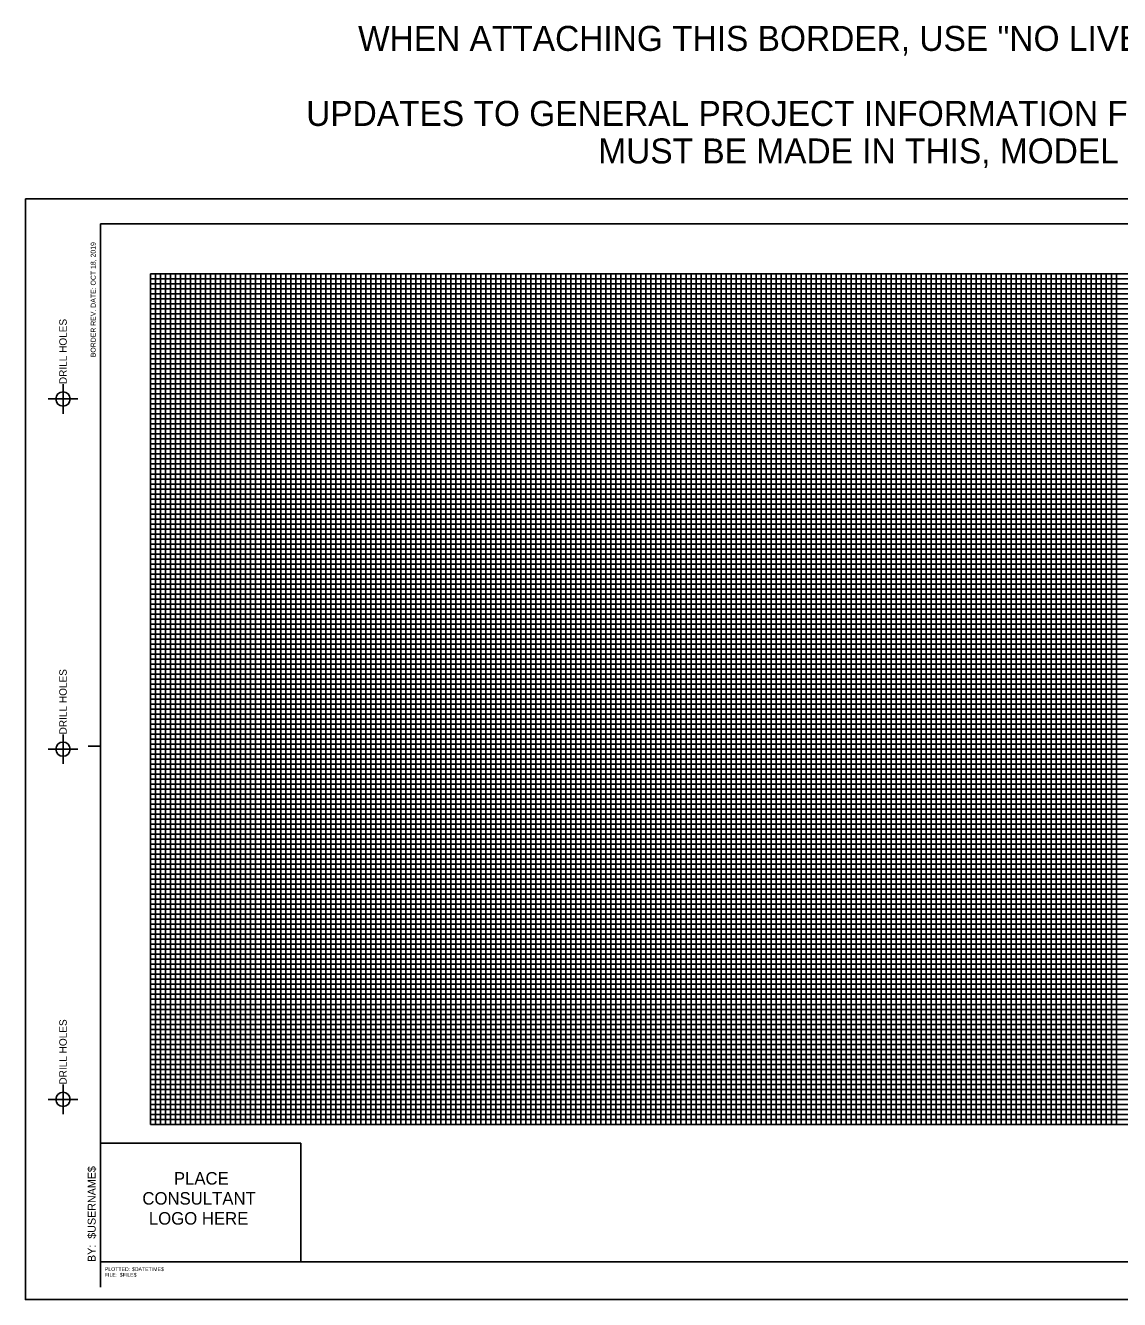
# Model space of a CAD drawing. Extents: x 0 to 34, y 0 to 25.5.
# Drawn here: x 0 to 21.86, y 0 to 25.46 of the extents above; entities that cross this region are included whole.
import ezdxf

# ---------------------------------------------------------------- set-up
doc = ezdxf.new("R2010")
doc.units = 0
for name, color, linetype in [('BORD-LINE', 7, 'Continuous'), ('CONS-LINE', 7, 'Continuous'), ('CONS-LOGO', 7, 'Continuous'), ('TTLB-TEXT', 7, 'Continuous'), ('USER-PAGE', 7, 'Continuous'), ('USER-TEXT', 7, 'Continuous'), ('XSEC-MAJR', 7, 'Continuous'), ('XSEC-MINR', 7, 'Continuous')]:
    doc.layers.add(name, color=color, linetype=linetype)

msp = doc.modelspace()

# ---------------------------------------------------------------- linework, layer by layer
at = {"layer": 'BORD-LINE'}
for p, q in [((33.5, 21.5), (1.5, 21.5)), ((1.5, 21.5), (1.5, 0.75)), ((1.5, 11.062), (1.25, 11.062)), ((1.5, 0.75), (33.5, 0.75)), ((1.5, 0.75), (1.5, 0.25))]:
    msp.add_line(p, q, dxfattribs=at)
at = {"layer": 'CONS-LINE'}
for p, q in [((1.5, 3.125), (5.5, 3.125)), ((5.5, 3.125), (5.5, 0.75))]:
    msp.add_line(p, q, dxfattribs=at)
at = {"layer": 'TTLB-TEXT'}
for p, q in [((0.75, 18.296), (0.75, 18)), ((0.454, 18), (1.046, 18)), ((0.75, 18), (0.75, 17.704)), ((0.75, 11.296), (0.75, 11)), ((1.046, 11), (0.454, 11)), ((0.75, 11), (0.75, 10.704)), ((0.75, 4.296), (0.75, 3.704)), ((0.454, 4), (1.046, 4))]:
    msp.add_line(p, q, dxfattribs=at)
for centre in [(0.75, 18), (0.75, 11), (0.75, 4)]:
    msp.add_circle(centre, 0.143, dxfattribs=at)
at = {"layer": 'USER-PAGE'}
msp.add_lwpolyline([(0, 22), (34, 22), (34, 0), (0, 0)], close=True, dxfattribs=at)
at = {"layer": 'XSEC-MAJR'}
for p, q in [((2.5, 20.5), (2.5, 3.5)), ((32.5, 20.5), (2.5, 20.5)), ((3.5, 20.5), (3.5, 3.5)), ((4.5, 20.5), (4.5, 3.5)), ((5.5, 20.5), (5.5, 3.5)), ((6.5, 20.5), (6.5, 3.5)), ((7.5, 20.5), (7.5, 3.5)), ((8.5, 20.5), (8.5, 3.5)), ((9.5, 20.5), (9.5, 3.5)), ((10.5, 20.5), (10.5, 3.5)), ((11.5, 20.5), (11.5, 3.5)), ((12.5, 20.5), (12.5, 3.5)), ((13.5, 20.5), (13.5, 3.5)), ((14.5, 20.5), (14.5, 3.5)), ((15.5, 20.5), (15.5, 3.5)), ((16.5, 20.5), (16.5, 3.5)), ((17.5, 20.5), (17.5, 3.5)), ((18.5, 20.5), (18.5, 3.5)), ((19.5, 20.5), (19.5, 3.5)), ((20.5, 20.5), (20.5, 3.5)), ((21.5, 20.5), (21.5, 3.5)), ((32.5, 19.5), (2.5, 19.5)), ((32.5, 18.5), (2.5, 18.5)), ((32.5, 17.5), (2.5, 17.5)), ((32.5, 16.5), (2.5, 16.5)), ((32.5, 15.5), (2.5, 15.5)), ((32.5, 14.5), (2.5, 14.5)), ((32.5, 13.5), (2.5, 13.5)), ((32.5, 12.5), (2.5, 12.5)), ((32.5, 11.5), (2.5, 11.5)), ((32.5, 10.5), (2.5, 10.5)), ((32.5, 9.5), (2.5, 9.5)), ((32.5, 8.5), (2.5, 8.5)), ((32.5, 7.5), (2.5, 7.5)), ((32.5, 6.5), (2.5, 6.5)), ((32.5, 5.5), (2.5, 5.5)), ((32.5, 4.5), (2.5, 4.5)), ((32.5, 3.5), (2.5, 3.5))]:
    msp.add_line(p, q, dxfattribs=at)
at = {"layer": 'XSEC-MINR'}
for p, q in [((32.5, 20.4), (2.5, 20.4)), ((2.6, 20.5), (2.6, 3.5)), ((2.7, 20.5), (2.7, 3.5)), ((2.8, 20.5), (2.8, 3.5)), ((2.9, 20.5), (2.9, 3.5)), ((3, 20.5), (3, 3.5)), ((3.1, 20.5), (3.1, 3.5)), ((3.2, 20.5), (3.2, 3.5)), ((3.3, 20.5), (3.3, 3.5)), ((3.4, 20.5), (3.4, 3.5)), ((3.6, 20.5), (3.6, 3.5)), ((3.7, 20.5), (3.7, 3.5)), ((3.8, 20.5), (3.8, 3.5)), ((3.9, 20.5), (3.9, 3.5)), ((4, 20.5), (4, 3.5)), ((4.1, 20.5), (4.1, 3.5)), ((4.2, 20.5), (4.2, 3.5)), ((4.3, 20.5), (4.3, 3.5)), ((4.4, 20.5), (4.4, 3.5)), ((4.6, 20.5), (4.6, 3.5)), ((4.7, 20.5), (4.7, 3.5)), ((4.8, 20.5), (4.8, 3.5)), ((4.9, 20.5), (4.9, 3.5)), ((5, 20.5), (5, 3.5)), ((5.1, 20.5), (5.1, 3.5)), ((5.2, 20.5), (5.2, 3.5)), ((5.3, 20.5), (5.3, 3.5)), ((5.4, 20.5), (5.4, 3.5)), ((5.6, 20.5), (5.6, 3.5)), ((5.7, 20.5), (5.7, 3.5)), ((5.8, 20.5), (5.8, 3.5)), ((5.9, 20.5), (5.9, 3.5)), ((6, 20.5), (6, 3.5)), ((6.1, 20.5), (6.1, 3.5)), ((6.2, 20.5), (6.2, 3.5)), ((6.3, 20.5), (6.3, 3.5)), ((6.4, 20.5), (6.4, 3.5)), ((6.6, 20.5), (6.6, 3.5)), ((6.7, 20.5), (6.7, 3.5)), ((6.8, 20.5), (6.8, 3.5)), ((6.9, 20.5), (6.9, 3.5)), ((7, 20.5), (7, 3.5)), ((7.1, 20.5), (7.1, 3.5)), ((7.2, 20.5), (7.2, 3.5)), ((7.3, 20.5), (7.3, 3.5)), ((7.4, 20.5), (7.4, 3.5)), ((7.6, 20.5), (7.6, 3.5)), ((7.7, 20.5), (7.7, 3.5)), ((7.8, 20.5), (7.8, 3.5)), ((7.9, 20.5), (7.9, 3.5)), ((8, 20.5), (8, 3.5)), ((8.1, 20.5), (8.1, 3.5)), ((8.2, 20.5), (8.2, 3.5)), ((8.3, 20.5), (8.3, 3.5)), ((8.4, 20.5), (8.4, 3.5)), ((8.6, 20.5), (8.6, 3.5)), ((8.7, 20.5), (8.7, 3.5)), ((8.8, 20.5), (8.8, 3.5)), ((8.9, 20.5), (8.9, 3.5)), ((9, 20.5), (9, 3.5)), ((9.1, 20.5), (9.1, 3.5)), ((9.2, 20.5), (9.2, 3.5)), ((9.3, 20.5), (9.3, 3.5)), ((9.4, 20.5), (9.4, 3.5)), ((9.6, 20.5), (9.6, 3.5)), ((9.7, 20.5), (9.7, 3.5)), ((9.8, 20.5), (9.8, 3.5)), ((9.9, 20.5), (9.9, 3.5)), ((10, 20.5), (10, 3.5)), ((10.1, 20.5), (10.1, 3.5)), ((10.2, 20.5), (10.2, 3.5)), ((10.3, 20.5), (10.3, 3.5)), ((10.4, 20.5), (10.4, 3.5)), ((10.6, 20.5), (10.6, 3.5)), ((10.7, 20.5), (10.7, 3.5)), ((10.8, 20.5), (10.8, 3.5)), ((10.9, 20.5), (10.9, 3.5)), ((11, 20.5), (11, 3.5)), ((11.1, 20.5), (11.1, 3.5)), ((11.2, 20.5), (11.2, 3.5)), ((11.3, 20.5), (11.3, 3.5)), ((11.4, 20.5), (11.4, 3.5)), ((11.6, 20.5), (11.6, 3.5)), ((11.7, 20.5), (11.7, 3.5)), ((11.8, 20.5), (11.8, 3.5)), ((11.9, 20.5), (11.9, 3.5)), ((12, 20.5), (12, 3.5)), ((12.1, 20.5), (12.1, 3.5)), ((12.2, 20.5), (12.2, 3.5)), ((12.3, 20.5), (12.3, 3.5)), ((12.4, 20.5), (12.4, 3.5)), ((12.6, 20.5), (12.6, 3.5)), ((12.7, 20.5), (12.7, 3.5)), ((12.8, 20.5), (12.8, 3.5)), ((12.9, 20.5), (12.9, 3.5)), ((13, 20.5), (13, 3.5)), ((13.1, 20.5), (13.1, 3.5)), ((13.2, 20.5), (13.2, 3.5)), ((13.3, 20.5), (13.3, 3.5)), ((13.4, 20.5), (13.4, 3.5)), ((13.6, 20.5), (13.6, 3.5)), ((13.7, 20.5), (13.7, 3.5)), ((13.8, 20.5), (13.8, 3.5)), ((13.9, 20.5), (13.9, 3.5)), ((14, 20.5), (14, 3.5)), ((14.1, 20.5), (14.1, 3.5)), ((14.2, 20.5), (14.2, 3.5)), ((14.3, 20.5), (14.3, 3.5)), ((14.4, 20.5), (14.4, 3.5)), ((14.6, 20.5), (14.6, 3.5)), ((14.7, 20.5), (14.7, 3.5)), ((14.8, 20.5), (14.8, 3.5)), ((14.9, 20.5), (14.9, 3.5)), ((15, 20.5), (15, 3.5)), ((15.1, 20.5), (15.1, 3.5)), ((15.2, 20.5), (15.2, 3.5)), ((15.3, 20.5), (15.3, 3.5)), ((15.4, 20.5), (15.4, 3.5)), ((15.6, 20.5), (15.6, 3.5)), ((15.7, 20.5), (15.7, 3.5)), ((15.8, 20.5), (15.8, 3.5)), ((15.9, 20.5), (15.9, 3.5)), ((16, 20.5), (16, 3.5)), ((16.1, 20.5), (16.1, 3.5)), ((16.2, 20.5), (16.2, 3.5)), ((16.3, 20.5), (16.3, 3.5)), ((16.4, 20.5), (16.4, 3.5)), ((16.6, 20.5), (16.6, 3.5)), ((16.7, 20.5), (16.7, 3.5)), ((16.8, 20.5), (16.8, 3.5)), ((16.9, 20.5), (16.9, 3.5)), ((17, 20.5), (17, 3.5)), ((17.1, 20.5), (17.1, 3.5)), ((17.2, 20.5), (17.2, 3.5)), ((17.3, 20.5), (17.3, 3.5)), ((17.4, 20.5), (17.4, 3.5)), ((17.6, 20.5), (17.6, 3.5)), ((17.7, 20.5), (17.7, 3.5)), ((17.8, 20.5), (17.8, 3.5)), ((17.9, 20.5), (17.9, 3.5)), ((18, 20.5), (18, 3.5)), ((18.1, 20.5), (18.1, 3.5)), ((18.2, 20.5), (18.2, 3.5)), ((18.3, 20.5), (18.3, 3.5)), ((18.4, 20.5), (18.4, 3.5)), ((18.6, 20.5), (18.6, 3.5)), ((18.7, 20.5), (18.7, 3.5)), ((18.8, 20.5), (18.8, 3.5)), ((18.9, 20.5), (18.9, 3.5)), ((19, 20.5), (19, 3.5)), ((19.1, 20.5), (19.1, 3.5)), ((19.2, 20.5), (19.2, 3.5)), ((19.3, 20.5), (19.3, 3.5)), ((19.4, 20.5), (19.4, 3.5)), ((19.6, 20.5), (19.6, 3.5)), ((19.7, 20.5), (19.7, 3.5)), ((19.8, 20.5), (19.8, 3.5)), ((19.9, 20.5), (19.9, 3.5)), ((20, 20.5), (20, 3.5)), ((20.1, 20.5), (20.1, 3.5)), ((20.2, 20.5), (20.2, 3.5)), ((20.3, 20.5), (20.3, 3.5)), ((20.4, 20.5), (20.4, 3.5)), ((20.6, 20.5), (20.6, 3.5)), ((20.7, 20.5), (20.7, 3.5)), ((20.8, 20.5), (20.8, 3.5)), ((20.9, 20.5), (20.9, 3.5)), ((21, 20.5), (21, 3.5)), ((21.1, 20.5), (21.1, 3.5)), ((21.2, 20.5), (21.2, 3.5)), ((21.3, 20.5), (21.3, 3.5)), ((21.4, 20.5), (21.4, 3.5)), ((21.6, 20.5), (21.6, 3.5)), ((21.7, 20.5), (21.7, 3.5)), ((21.8, 20.5), (21.8, 3.5)), ((32.5, 20.3), (2.5, 20.3)), ((32.5, 20.2), (2.5, 20.2)), ((32.5, 20.1), (2.5, 20.1)), ((32.5, 20), (2.5, 20)), ((32.5, 19.9), (2.5, 19.9)), ((32.5, 19.8), (2.5, 19.8)), ((32.5, 19.7), (2.5, 19.7)), ((32.5, 19.6), (2.5, 19.6)), ((32.5, 19.4), (2.5, 19.4)), ((32.5, 19.3), (2.5, 19.3)), ((32.5, 19.2), (2.5, 19.2)), ((32.5, 19.1), (2.5, 19.1)), ((32.5, 19), (2.5, 19)), ((32.5, 18.9), (2.5, 18.9)), ((32.5, 18.8), (2.5, 18.8)), ((32.5, 18.7), (2.5, 18.7)), ((32.5, 18.6), (2.5, 18.6)), ((32.5, 18.4), (2.5, 18.4)), ((32.5, 18.3), (2.5, 18.3)), ((32.5, 18.2), (2.5, 18.2)), ((32.5, 18.1), (2.5, 18.1)), ((32.5, 18), (2.5, 18)), ((32.5, 17.9), (2.5, 17.9)), ((32.5, 17.8), (2.5, 17.8)), ((32.5, 17.7), (2.5, 17.7)), ((32.5, 17.6), (2.5, 17.6)), ((32.5, 17.4), (2.5, 17.4)), ((32.5, 17.3), (2.5, 17.3)), ((32.5, 17.2), (2.5, 17.2)), ((32.5, 17.1), (2.5, 17.1)), ((32.5, 17), (2.5, 17)), ((32.5, 16.9), (2.5, 16.9)), ((32.5, 16.8), (2.5, 16.8)), ((32.5, 16.7), (2.5, 16.7)), ((32.5, 16.6), (2.5, 16.6)), ((32.5, 16.4), (2.5, 16.4)), ((32.5, 16.3), (2.5, 16.3)), ((32.5, 16.2), (2.5, 16.2)), ((32.5, 16.1), (2.5, 16.1)), ((32.5, 16), (2.5, 16)), ((32.5, 15.9), (2.5, 15.9)), ((32.5, 15.8), (2.5, 15.8)), ((32.5, 15.7), (2.5, 15.7)), ((32.5, 15.6), (2.5, 15.6)), ((32.5, 15.4), (2.5, 15.4)), ((32.5, 15.3), (2.5, 15.3)), ((32.5, 15.2), (2.5, 15.2)), ((32.5, 15.1), (2.5, 15.1)), ((32.5, 15), (2.5, 15)), ((32.5, 14.9), (2.5, 14.9)), ((32.5, 14.8), (2.5, 14.8)), ((32.5, 14.7), (2.5, 14.7)), ((32.5, 14.6), (2.5, 14.6)), ((32.5, 14.4), (2.5, 14.4)), ((32.5, 14.4), (2.5, 14.4)), ((32.5, 14.3), (2.5, 14.3)), ((32.5, 14.3), (2.5, 14.3)), ((32.5, 14.2), (2.5, 14.2)), ((32.5, 14.2), (2.5, 14.2)), ((32.5, 14.1), (2.5, 14.1)), ((32.5, 14.1), (2.5, 14.1)), ((32.5, 14), (2.5, 14)), ((32.5, 14), (2.5, 14)), ((32.5, 13.9), (2.5, 13.9)), ((32.5, 13.9), (2.5, 13.9)), ((32.5, 13.8), (2.5, 13.8)), ((32.5, 13.8), (2.5, 13.8)), ((32.5, 13.7), (2.5, 13.7)), ((32.5, 13.7), (2.5, 13.7)), ((32.5, 13.6), (2.5, 13.6)), ((32.5, 13.6), (2.5, 13.6)), ((32.5, 13.4), (2.5, 13.4)), ((32.5, 13.3), (2.5, 13.3)), ((32.5, 13.2), (2.5, 13.2)), ((32.5, 13.1), (2.5, 13.1)), ((32.5, 13), (2.5, 13)), ((32.5, 12.9), (2.5, 12.9)), ((32.5, 12.8), (2.5, 12.8)), ((32.5, 12.7), (2.5, 12.7)), ((32.5, 12.6), (2.5, 12.6)), ((32.5, 12.4), (2.5, 12.4)), ((32.5, 12.3), (2.5, 12.3)), ((32.5, 12.2), (2.5, 12.2)), ((32.5, 12.1), (2.5, 12.1)), ((32.5, 12), (2.5, 12)), ((32.5, 11.9), (2.5, 11.9)), ((32.5, 11.8), (2.5, 11.8)), ((32.5, 11.7), (2.5, 11.7)), ((32.5, 11.6), (2.5, 11.6)), ((32.5, 11.4), (2.5, 11.4)), ((32.5, 11.4), (2.5, 11.4)), ((32.5, 11.3), (2.5, 11.3)), ((32.5, 11.3), (2.5, 11.3)), ((32.5, 11.2), (2.5, 11.2)), ((32.5, 11.2), (2.5, 11.2)), ((32.5, 11.1), (2.5, 11.1)), ((32.5, 11.1), (2.5, 11.1)), ((32.5, 11), (2.5, 11)), ((32.5, 11), (2.5, 11)), ((32.5, 10.9), (2.5, 10.9)), ((32.5, 10.9), (2.5, 10.9)), ((32.5, 10.8), (2.5, 10.8)), ((32.5, 10.8), (2.5, 10.8)), ((32.5, 10.7), (2.5, 10.7)), ((32.5, 10.7), (2.5, 10.7)), ((32.5, 10.6), (2.5, 10.6)), ((32.5, 10.6), (2.5, 10.6)), ((32.5, 10.4), (2.5, 10.4)), ((32.5, 10.3), (2.5, 10.3)), ((32.5, 10.2), (2.5, 10.2)), ((32.5, 10.1), (2.5, 10.1)), ((32.5, 10), (2.5, 10)), ((32.5, 9.9), (2.5, 9.9)), ((32.5, 9.8), (2.5, 9.8)), ((32.5, 9.7), (2.5, 9.7)), ((32.5, 9.6), (2.5, 9.6)), ((32.5, 9.4), (2.5, 9.4)), ((32.5, 9.3), (2.5, 9.3)), ((32.5, 9.2), (2.5, 9.2)), ((32.5, 9.1), (2.5, 9.1)), ((32.5, 9), (2.5, 9)), ((32.5, 8.9), (2.5, 8.9)), ((32.5, 8.8), (2.5, 8.8)), ((32.5, 8.7), (2.5, 8.7)), ((32.5, 8.6), (2.5, 8.6)), ((32.5, 8.4), (2.5, 8.4)), ((32.5, 8.4), (2.5, 8.4)), ((32.5, 8.3), (2.5, 8.3)), ((32.5, 8.3), (2.5, 8.3)), ((32.5, 8.2), (2.5, 8.2)), ((32.5, 8.2), (2.5, 8.2)), ((32.5, 8.1), (2.5, 8.1)), ((32.5, 8.1), (2.5, 8.1)), ((32.5, 8), (2.5, 8)), ((32.5, 8), (2.5, 8)), ((32.5, 7.9), (2.5, 7.9)), ((32.5, 7.9), (2.5, 7.9)), ((32.5, 7.8), (2.5, 7.8)), ((32.5, 7.8), (2.5, 7.8)), ((32.5, 7.7), (2.5, 7.7)), ((32.5, 7.7), (2.5, 7.7)), ((32.5, 7.6), (2.5, 7.6)), ((32.5, 7.6), (2.5, 7.6)), ((32.5, 7.4), (2.5, 7.4)), ((32.5, 7.3), (2.5, 7.3)), ((32.5, 7.2), (2.5, 7.2)), ((32.5, 7.1), (2.5, 7.1)), ((32.5, 7), (2.5, 7)), ((32.5, 6.9), (2.5, 6.9)), ((32.5, 6.8), (2.5, 6.8)), ((32.5, 6.7), (2.5, 6.7)), ((32.5, 6.6), (2.5, 6.6)), ((32.5, 6.4), (2.5, 6.4)), ((32.5, 6.3), (2.5, 6.3)), ((32.5, 6.2), (2.5, 6.2)), ((32.5, 6.1), (2.5, 6.1)), ((32.5, 6), (2.5, 6)), ((32.5, 5.9), (2.5, 5.9)), ((32.5, 5.8), (2.5, 5.8)), ((32.5, 5.7), (2.5, 5.7)), ((32.5, 5.6), (2.5, 5.6)), ((32.5, 5.4), (2.5, 5.4)), ((32.5, 5.3), (2.5, 5.3)), ((32.5, 5.2), (2.5, 5.2)), ((32.5, 5.1), (2.5, 5.1)), ((32.5, 5), (2.5, 5)), ((32.5, 4.9), (2.5, 4.9)), ((32.5, 4.8), (2.5, 4.8)), ((32.5, 4.7), (2.5, 4.7)), ((32.5, 4.6), (2.5, 4.6)), ((32.5, 4.4), (2.5, 4.4)), ((32.5, 4.3), (2.5, 4.3)), ((32.5, 4.2), (2.5, 4.2)), ((32.5, 4.1), (2.5, 4.1)), ((32.5, 4), (2.5, 4)), ((32.5, 3.9), (2.5, 3.9)), ((32.5, 3.8), (2.5, 3.8)), ((32.5, 3.7), (2.5, 3.7)), ((32.5, 3.6), (2.5, 3.6))]:
    msp.add_line(p, q, dxfattribs=at)

# ---------------------------------------------------------------- texts
at = {"layer": 'CONS-LOGO'}
for s, p in [('PLACE', (2.966, 2.297)), ('CONSULTANT', (2.336, 1.897)), ('LOGO HERE', (2.466, 1.497))]:
    msp.add_text(s, height=0.25, dxfattribs=at).set_placement(p)
at = {"layer": 'TTLB-TEXT'}
for s, height, rotation, p in [('$USERNAME$', 0.16, 90, (1.403, 1.215)), ('$USERNAME$', 0.16, 90, (1.403, 1.215)), ('BY:', 0.16, 90, (1.403, 0.75)), ('BY:', 0.16, 90, (1.403, 0.75)), ('PLOTTED:', 0.075, 360, (1.586, 0.57)), ('FILE:', 0.075, 360, (1.586, 0.455)), ('$FILE$', 0.075, 360, (1.885, 0.455)), ('$DATETIME$', 0.075, 360, (2.127, 0.57))]:
    msp.add_text(s, height=height, rotation=rotation, dxfattribs=at).set_placement(p)
at = {"layer": 'USER-TEXT'}
for s, p in [('WHEN ATTACHING THIS BORDER, USE "NO LIVE NESTING".', (6.646, 24.957)), ('UPDATES TO GENERAL PROJECT INFORMATION FOR THIS BORDER', (5.609, 23.457)), ('MUST BE MADE IN THIS, MODEL', (11.447, 22.707))]:
    msp.add_text(s, height=0.5, dxfattribs=at).set_placement(p)
for s, height, p in [('BORDER REV. DATE: OCT 18, 2019', 0.1, (1.403, 18.833)), ('DRILL HOLES', 0.15, (0.825, 18.296)), ('DRILL HOLES', 0.15, (0.825, 11.296)), ('DRILL HOLES', 0.15, (0.825, 4.296))]:
    msp.add_text(s, height=height, rotation=90, dxfattribs=at).set_placement(p)

doc.saveas('drawing.dxf')
